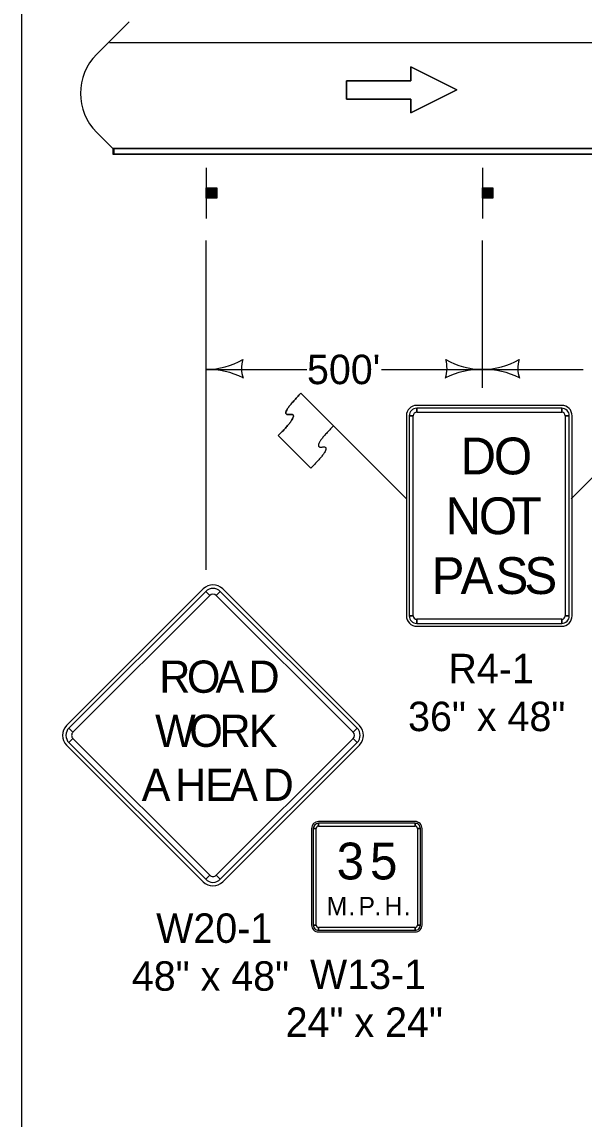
# Model space of a CAD drawing. Extents: x -2134934 to -2122394, y -2140205 to -2137036.
# Drawn here: x -2130232 to -2129927, y -2138192 to -2137596 of the extents above; entities that cross this region are included whole.
import ezdxf

# ---------------------------------------------------------------- set-up
doc = ezdxf.new("R2010")
doc.units = 0
for name, color, linetype in [('Barrier', 7, 'Continuous'), ('BridgeSuperStructureExisting', 7, 'Continuous'), ('Default', 7, 'Continuous'), ('DsnShtPlotIdentification', 7, 'Continuous'), ('TC_Barrier', 7, 'Continuous')]:
    doc.layers.add(name, color=color, linetype=linetype)

msp = doc.modelspace()

# ---------------------------------------------------------------- linework, layer by layer
at = {"layer": 'Barrier'}
for p, q in [((-2130023.11, -2137855.42), (-2130080.45, -2137798.12)), ((-2130080.45, -2137798.12), (-2130062.76, -2137815.8)), ((-2129933.82, -2137855.42), (-2129876.5, -2137798.11)), ((-2129938.87, -2137804.67), (-2130017.62, -2137804.67)), ((-2130017.62, -2137808.42), (-2130017.62, -2137806.23)), ((-2129938.87, -2137806.23), (-2129938.87, -2137808.42)), ((-2130023.24, -2137810.29), (-2130023.24, -2137919.04)), ((-2130021.68, -2137810.29), (-2130019.49, -2137810.29)), ((-2129936.99, -2137810.29), (-2129934.81, -2137810.29)), ((-2129933.24, -2137919.04), (-2129933.24, -2137810.29)), ((-2130075.13, -2137838.79), (-2130092.81, -2137821.12)), ((-2130133.53, -2137904.4), (-2130207.78, -2137978.64)), ((-2130048.68, -2137978.64), (-2130122.92, -2137904.4)), ((-2130132.2, -2137905.72), (-2130129.99, -2137907.93)), ((-2130126.46, -2137907.93), (-2130124.25, -2137905.72)), ((-2130019.49, -2137919.04), (-2130021.68, -2137919.04)), ((-2130017.62, -2137923.1), (-2130017.62, -2137920.91)), ((-2129938.87, -2137920.91), (-2129938.87, -2137923.1)), ((-2129934.81, -2137919.04), (-2129936.99, -2137919.04)), ((-2130017.62, -2137924.66), (-2129938.87, -2137924.66)), ((-2130204.24, -2137982.18), (-2130206.45, -2137979.97)), ((-2130050, -2137979.97), (-2130052.21, -2137982.18)), ((-2130206.45, -2137987.92), (-2130204.24, -2137985.71)), ((-2130052.21, -2137985.71), (-2130050, -2137987.92)), ((-2130207.78, -2137989.25), (-2130133.53, -2138063.5)), ((-2130122.92, -2138063.5), (-2130048.68, -2137989.25)), ((-2130018.46, -2138030.77), (-2130070.95, -2138030.77)), ((-2130074.7, -2138034.52), (-2130074.7, -2138087.02)), ((-2130073.77, -2138034.52), (-2130072.2, -2138034.52)), ((-2130070.95, -2138033.27), (-2130070.95, -2138031.71)), ((-2130018.46, -2138031.71), (-2130018.46, -2138033.27)), ((-2130017.21, -2138034.52), (-2130015.64, -2138034.52)), ((-2130014.71, -2138087.02), (-2130014.71, -2138034.52)), ((-2130129.99, -2138059.96), (-2130132.2, -2138062.17)), ((-2130124.25, -2138062.17), (-2130126.46, -2138059.96)), ((-2130072.2, -2138087.02), (-2130073.77, -2138087.02)), ((-2130070.95, -2138089.83), (-2130070.95, -2138088.27)), ((-2130018.46, -2138088.27), (-2130018.46, -2138089.83)), ((-2130015.64, -2138087.02), (-2130017.21, -2138087.02)), ((-2130070.95, -2138090.77), (-2130018.46, -2138090.77))]:
    msp.add_line(p, q, dxfattribs=at)
for points in [[(-2129938.87, -2137806.23), (-2130017.62, -2137806.23), (-2130017.62, -2137808.42), (-2129938.87, -2137808.42), (-2129938.87, -2137806.23)], [(-2130021.68, -2137810.29), (-2130021.68, -2137919.04), (-2130019.49, -2137919.04), (-2130019.49, -2137810.29), (-2130021.68, -2137810.29)], [(-2129934.81, -2137919.04), (-2129934.81, -2137810.29), (-2129936.99, -2137810.29), (-2129936.99, -2137919.04), (-2129934.81, -2137919.04)], [(-2130132.2, -2137905.72), (-2130206.45, -2137979.97), (-2130204.24, -2137982.18), (-2130129.99, -2137907.93), (-2130132.2, -2137905.72)], [(-2130050, -2137979.97), (-2130124.25, -2137905.72), (-2130126.46, -2137907.93), (-2130052.21, -2137982.18), (-2130050, -2137979.97)], [(-2130017.62, -2137923.1), (-2129938.87, -2137923.1), (-2129938.87, -2137920.91), (-2130017.62, -2137920.91), (-2130017.62, -2137923.1)], [(-2130206.45, -2137987.92), (-2130132.2, -2138062.17), (-2130129.99, -2138059.96), (-2130204.24, -2137985.71), (-2130206.45, -2137987.92)], [(-2130124.25, -2138062.17), (-2130050, -2137987.92), (-2130052.21, -2137985.71), (-2130126.46, -2138059.96), (-2130124.25, -2138062.17)], [(-2130073.77, -2138034.52), (-2130073.77, -2138087.02), (-2130072.2, -2138087.02), (-2130072.2, -2138034.52), (-2130073.77, -2138034.52)], [(-2130018.46, -2138031.71), (-2130070.95, -2138031.71), (-2130070.95, -2138033.27), (-2130018.46, -2138033.27), (-2130018.46, -2138031.71)], [(-2130015.64, -2138087.02), (-2130015.64, -2138034.52), (-2130017.21, -2138034.52), (-2130017.21, -2138087.02), (-2130015.64, -2138087.02)], [(-2130070.95, -2138089.83), (-2130018.46, -2138089.83), (-2130018.46, -2138088.27), (-2130070.95, -2138088.27), (-2130070.95, -2138089.83)]]:
    msp.add_lwpolyline(points, close=True, dxfattribs=at)
for centre, radius, start, end in [((-2130017.62, -2137810.29), 5.62, 90.00021, 179.99985), ((-2130017.62, -2137810.29), 4.06, 90.00021, 179.99985), ((-2130017.62, -2137810.29), 1.87, 90.00021, 179.99985), ((-2129938.87, -2137810.29), 5.62, 0, 90.00021), ((-2129938.87, -2137810.29), 4.06, 0, 90.00021), ((-2129938.87, -2137810.29), 1.87, 0, 90.00021), ((-2130128.23, -2137909.7), 7.5, 44.99999, 134.99974), ((-2130128.23, -2137909.7), 5.62, 44.99999, 134.99974), ((-2130128.23, -2137909.7), 2.5, 44.99999, 134.99974), ((-2130017.62, -2137919.04), 5.62, 179.99985, 270.00006), ((-2130017.62, -2137919.04), 4.06, 179.99985, 270.00006), ((-2130017.62, -2137919.04), 1.87, 179.99985, 270.00006), ((-2129938.87, -2137919.04), 5.62, 270.00006, 0.00027), ((-2129938.87, -2137919.04), 4.06, 270.00006, 0.00027), ((-2129938.87, -2137919.04), 1.87, 270.00006, 0.00027), ((-2130202.47, -2137983.95), 7.5, 134.99974, 224.99995), ((-2130202.47, -2137983.95), 5.62, 134.99974, 224.99995), ((-2130202.47, -2137983.95), 2.5, 134.99974, 224.99995), ((-2130053.98, -2137983.95), 2.5, 315.00016, 44.9998), ((-2130053.98, -2137983.95), 5.62, 315.00016, 44.9998), ((-2130053.98, -2137983.95), 7.5, 315.00016, 44.9998), ((-2130070.95, -2138034.52), 3.75, 90.00021, 179.99985), ((-2130018.46, -2138034.52), 3.75, 0, 90.00021), ((-2130070.95, -2138034.52), 2.81, 90.00021, 179.99985), ((-2130070.95, -2138034.52), 1.25, 90.00021, 179.99985), ((-2130018.46, -2138034.52), 2.81, 0, 90.00021), ((-2130018.46, -2138034.52), 1.25, 0, 90.00021), ((-2130128.23, -2138058.19), 2.5, 224.99995, 315.00016), ((-2130128.23, -2138058.19), 7.5, 224.99995, 315.00016), ((-2130128.23, -2138058.19), 5.62, 224.99995, 315.00016), ((-2130070.95, -2138087.02), 3.75, 179.99985, 270.00006), ((-2130070.95, -2138087.02), 2.81, 179.99985, 270.00006), ((-2130070.95, -2138087.02), 1.25, 179.99985, 270.00006), ((-2130018.46, -2138087.02), 3.75, 270.00006, 0.00027), ((-2130018.46, -2138087.02), 2.81, 270.00006, 0.00027), ((-2130018.46, -2138087.02), 1.25, 270.00006, 0.00027)]:
    msp.add_arc(centre, radius, start, end, dxfattribs=at)
for points in [[(-2130092.81, -2137821.12), (-2130080.44, -2137808.74), (-2130092.82, -2137810.51), (-2130080.45, -2137798.12)], [(-2130062.76, -2137815.8), (-2130075.13, -2137828.19), (-2130062.76, -2137826.41), (-2130075.13, -2137838.79)]]:
    msp.add_open_spline(points, degree=2, dxfattribs=at)
at = {"layer": 'BridgeSuperStructureExisting'}
for p, q in [((-2130173.78, -2137596.37), (-2130191.36, -2137613.95)), ((-2130173.79, -2137596.38), (-2130191.36, -2137613.95)), ((-2130191.36, -2137656.37), (-2130182.57, -2137665.16)), ((-2130191.36, -2137656.38), (-2130182.57, -2137665.16)), ((-2130182.57, -2137665.16), (-2128870.12, -2137665.16)), ((-2130131.95, -2137675.66), (-2130131.95, -2137703.16)), ((-2129981.95, -2137675.66), (-2129981.95, -2137703.16)), ((-2130131.54, -2137692.11), (-2130131.54, -2137686.52)), ((-2130131.26, -2137686.52), (-2130131.26, -2137692.11)), ((-2130130.99, -2137692.11), (-2130130.99, -2137686.52)), ((-2130130.73, -2137686.52), (-2130130.73, -2137692.11)), ((-2130130.51, -2137692.11), (-2130130.51, -2137686.52)), ((-2130130.3, -2137686.52), (-2130130.3, -2137692.11)), ((-2130129.96, -2137692.11), (-2130129.96, -2137686.52)), ((-2130129.7, -2137686.52), (-2130129.7, -2137692.11)), ((-2130129.47, -2137692.11), (-2130129.49, -2137686.52)), ((-2130129.16, -2137686.52), (-2130129.16, -2137692.11)), ((-2130128.78, -2137692.11), (-2130128.78, -2137686.52)), ((-2130128.35, -2137686.52), (-2130128.35, -2137692.11)), ((-2130128.12, -2137692.11), (-2130128.14, -2137686.52)), ((-2130127.71, -2137686.52), (-2130127.69, -2137692.11)), ((-2130127.49, -2137692.11), (-2130127.49, -2137686.52)), ((-2130127.17, -2137686.52), (-2130127.17, -2137692.11)), ((-2130126.94, -2137692.11), (-2130126.94, -2137686.52)), ((-2130126.62, -2137686.52), (-2130126.62, -2137692.11)), ((-2129981.54, -2137692.11), (-2129981.54, -2137686.52)), ((-2129981.26, -2137686.52), (-2129981.26, -2137692.11)), ((-2129980.99, -2137692.11), (-2129980.99, -2137686.52)), ((-2129980.73, -2137686.52), (-2129980.73, -2137692.11)), ((-2129980.51, -2137692.11), (-2129980.51, -2137686.52)), ((-2129980.3, -2137686.52), (-2129980.3, -2137692.11)), ((-2129979.96, -2137692.11), (-2129979.96, -2137686.52)), ((-2129979.7, -2137686.52), (-2129979.7, -2137692.11)), ((-2129979.47, -2137692.11), (-2129979.49, -2137686.52)), ((-2129979.16, -2137686.52), (-2129979.16, -2137692.11)), ((-2129978.78, -2137692.11), (-2129978.78, -2137686.52)), ((-2129978.35, -2137686.52), (-2129978.35, -2137692.11)), ((-2129978.12, -2137692.11), (-2129978.14, -2137686.52)), ((-2129977.71, -2137686.52), (-2129977.69, -2137692.11)), ((-2129977.49, -2137692.11), (-2129977.49, -2137686.52)), ((-2129977.17, -2137686.52), (-2129977.17, -2137692.11)), ((-2129976.94, -2137692.11), (-2129976.94, -2137686.52)), ((-2129976.62, -2137686.52), (-2129976.62, -2137692.11)), ((-2130131.95, -2137893.97), (-2130131.95, -2137715.16)), ((-2129981.95, -2137795.16), (-2129981.95, -2137715.16)), ((-2130131.95, -2137785.16), (-2130077.2, -2137785.16)), ((-2130036.7, -2137785.16), (-2129981.95, -2137785.16)), ((-2129981.95, -2137785.16), (-2129927.2, -2137785.16))]:
    msp.add_line(p, q, dxfattribs=at)
for points in [[(-2130055.82, -2137628.32), (-2130055.82, -2137638.32), (-2130020.82, -2137638.32), (-2130020.82, -2137645.82), (-2129995.82, -2137633.32), (-2130020.82, -2137620.82), (-2130020.82, -2137628.32)], [(-2130131.86, -2137692.11), (-2130131.86, -2137686.48), (-2130126.23, -2137686.48), (-2130126.23, -2137692.11)], [(-2129981.86, -2137692.11), (-2129981.86, -2137686.48), (-2129976.23, -2137686.48), (-2129976.23, -2137692.11)]]:
    msp.add_lwpolyline(points, close=True, dxfattribs=at)
msp.add_lwpolyline([(-2130020.82, -2137628.32), (-2130020.82, -2137620.82), (-2129995.82, -2137633.32), (-2130020.82, -2137645.82), (-2130020.82, -2137638.32), (-2130055.82, -2137638.32), (-2130055.82, -2137628.32), (-2130020.82, -2137628.32)], dxfattribs=at)
for centre, radius, start, end in [((-2130170.14, -2137635.16), 30, 135, 225), ((-2130170.14, -2137635.16), 30, 135, 225), ((-2130132.71, -2137742.67), 42.5, 271.0176, 299.07249), ((-2130096.33, -2137784.54), 16.42, 163.26665, 198.73335), ((-2130017.57, -2137784.54), 16.42, 341.26665, 16.73335), ((-2129981.2, -2137742.67), 42.5, 240.92751, 268.9824), ((-2129982.71, -2137742.67), 42.5, 271.0176, 299.07249), ((-2129946.33, -2137784.54), 16.42, 163.26665, 198.73335), ((-2130131.22, -2137827.65), 42.5, 62.92751, 90.9824), ((-2129982.68, -2137827.65), 42.5, 89.0176, 117.07249), ((-2129981.22, -2137827.65), 42.5, 62.92751, 90.9824)]:
    msp.add_arc(centre, radius, start, end, dxfattribs=at)
at = {"layer": 'Default'}
msp.add_lwpolyline([(-2130231.95, -2137035.95), (-2127096.96, -2137035.95), (-2127096.96, -2139045.94), (-2130231.95, -2139045.94)], close=True, dxfattribs=at)
at = {"layer": 'DsnShtPlotIdentification'}
for p, q in [((-2129531.95, -2137607.66), (-2130184.45, -2137607.66)), ((-2129535.12, -2137665.16), (-2130182.57, -2137665.16)), ((-2130182.57, -2137665.16), (-2130182.57, -2137668.16)), ((-2130181.95, -2137665.16), (-2128681.95, -2137665.16)), ((-2130181.95, -2137668.16), (-2130181.95, -2137665.16)), ((-2130182.57, -2137668.16), (-2129497.55, -2137668.16))]:
    msp.add_line(p, q, dxfattribs=at)
for points in [[(-2128870.12, -2137665.16), (-2130182.57, -2137665.16)], [(-2128870.12, -2137668.16), (-2130182.57, -2137668.16)]]:
    msp.add_lwpolyline(points, dxfattribs=at)
at = {"layer": 'TC_Barrier'}
msp.add_line((-2130092.81, -2137821.12), (-2130075.13, -2137838.79), dxfattribs=at)
for points in [[(-2130080.45, -2137798.12), (-2130092.82, -2137810.51), (-2130080.44, -2137808.74), (-2130092.81, -2137821.12)], [(-2130062.76, -2137815.8), (-2130075.13, -2137828.19), (-2130062.76, -2137826.41), (-2130075.13, -2137838.79)]]:
    msp.add_open_spline(points, degree=2, dxfattribs=at)

# ---------------------------------------------------------------- texts
at = {"layer": 'Barrier'}
for s, height, p in [('D', 20, (-2129993.87, -2137842.17)), ('O', 20, (-2129975.74, -2137842.17)), ('N', 20, (-2130001.99, -2137874.67)), ('O', 20, (-2129983.87, -2137874.67)), ('T', 20, (-2129966.06, -2137874.67)), ('P', 20, (-2130009.51, -2137907.17)), ('A', 20, (-2129993.82, -2137907.17)), ('S', 20, (-2129974.85, -2137907.17)), ('S', 20, (-2129959.17, -2137907.17)), ('R4-1', 16, (-2130000.41, -2137955.66)), ('R', 17.5, (-2130157.39, -2137960.82)), ('O', 17.5, (-2130142.38, -2137960.82)), ('A', 17.5, (-2130126.83, -2137960.82)), ('D', 17.5, (-2130108.95, -2137960.82)), ('36" x 48"', 16, (-2130022.31, -2137981.66)), ('W', 17.5, (-2130159.67, -2137990.2)), ('O', 17.5, (-2130141.08, -2137990.2)), ('R', 17.5, (-2130124.67, -2137990.2)), ('K', 17.5, (-2130108.81, -2137990.2)), ('A', 17.5, (-2130166.95, -2138019.57)), ('H', 17.5, (-2130148.74, -2138019.57)), ('E', 17.5, (-2130132.51, -2138019.57)), ('A', 17.5, (-2130119.47, -2138019.57)), ('D', 17.5, (-2130101.26, -2138019.57)), ('3', 20, (-2130061.09, -2138062.23)), ('5', 20, (-2130042.97, -2138062.23)), ('M', 10, (-2130066.48, -2138081.71)), ('P', 10, (-2130049.23, -2138081.71)), ('H', 10, (-2130035.11, -2138081.71)), ('W20-1', 16, (-2130159.08, -2138096.69)), ('.', 10, (-2130054.68, -2138081.71)), ('.', 10, (-2130040.57, -2138081.71)), ('.', 10, (-2130024.64, -2138081.71)), ('48" x 48"', 16, (-2130172.29, -2138122.69)), ('W13-1', 16, (-2130075.56, -2138121.77)), ('24" x 24"', 16, (-2130088.77, -2138147.77))]:
    msp.add_text(s, height=height, dxfattribs=at).set_placement(p)
at = {"layer": 'BridgeSuperStructureExisting'}
msp.add_text("500'", height=16, dxfattribs=at).set_placement((-2130077.2, -2137793.16))

doc.saveas('drawing.dxf')
